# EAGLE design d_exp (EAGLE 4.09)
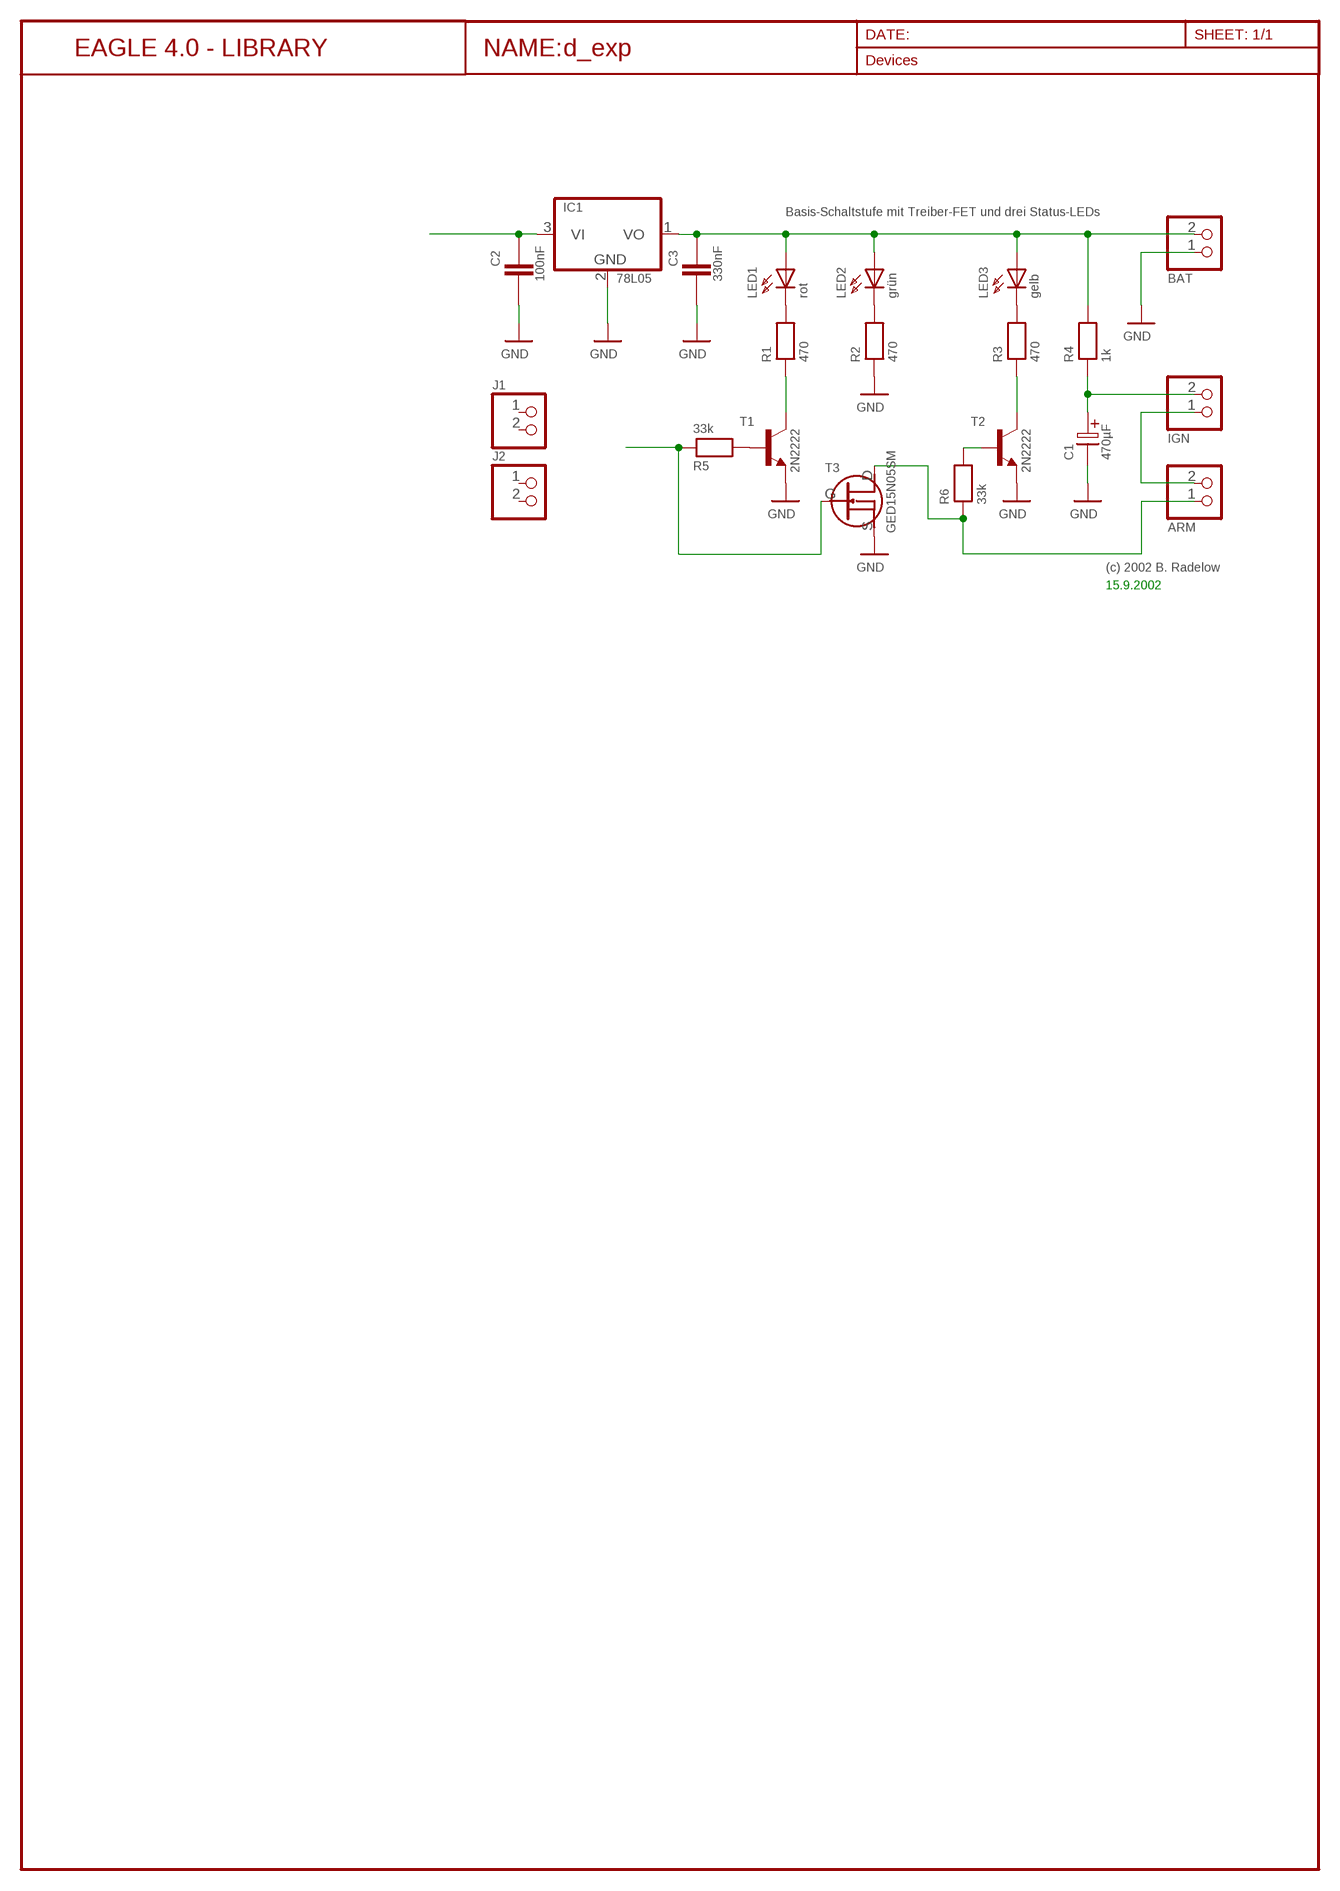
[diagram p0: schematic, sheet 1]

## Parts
ARM  PFOSTEN_1X2  [1X02]
BAT  PFOSTEN_1X2  [1X02]
C1  470µF  EC_470U  [E5-10,5]
C2  100nF  MKS2_10N-150N  [C5B2.5]
C3  330nF  MKS2_330N  [C5B3.5]
IC1  78L05  [TO92]
IGN  PFOSTEN_1X2  [1X02]
J1  PFOSTEN_1X2  [1X02]
J2  PFOSTEN_1X2  [1X02]
LED1  rot  LED_3MM  [LED3MM]
LED2  grün  LED_3MM  [LED3MM]
LED3  gelb  LED_3MM  [LED3MM]
R1  470  R7,5  [0207/7]
R2  470  R7,5  [0207/7]
R3  470  R7,5  [0207/7]
R4  1k  R7,5  [0207/7]
R5  33k  R7,5  [0207/7]
R6  33k  R7,5  [0207/7]
T1  2N2222  [TO18]
T2  2N2222  [TO18]
T3  GED15N05SM  [TO252]

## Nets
5VOLT: C2.1 IC1.3(VI)
GND: BAT.1 C1.- C2.2 C3.2 IC1.2(GND) R2.1 T1.1(E) T2.1(E) T3.S
N$1: ARM.2 IGN.1
N$2: LED2.K(C) R2.2
N$3: LED1.K(C) R1.2
N$4: LED3.K(C) R3.2
N$6: R5.1 T3.G
N$8: ARM.1 R6.1 T3.D
N$11: C1.+ IGN.2 R4.1
N$17: R1.1 T1.3(C)
N$25: R3.1 T2.3(C)
N$27: R6.2 T2.2(B)
N$29: R5.2 T1.2(B)
V+: BAT.2 C3.1 IC1.1(VO) LED1.A LED2.A LED3.A R4.2
Unconnected: J1.1 J1.2 J2.1 J2.2

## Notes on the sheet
- Basis-Schaltstufe mit Treiber-FET und drei Status-LEDs
- (c) 2002 B. Radelow
- 15.9.2002

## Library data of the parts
ARM BAT IGN J1 J2 = _d_serie:PFOSTEN_1X2: Pfosten 2x1
C1 = _d_serie:EC_470U: 470µF 16V, Höhe 17mm
C2 = _d_serie:MKS2_10N-150N: WIMA MKS2 Folienkondensator
C3 = _d_serie:MKS2_330N: WIMA MKS2 Folienkondensator 330nF
IC1 = _d_serie:78L05: Voltage Regulator 5V
LED1-LED3 = _d_serie:LED_3MM
R1-R6 = _d_serie:R7,5: Widerstand 0,3 Watt liegend
T1 T2 = _d_serie:2N2222
T3 = _d_serie:GED15N05SM: N-Channel Power-FET

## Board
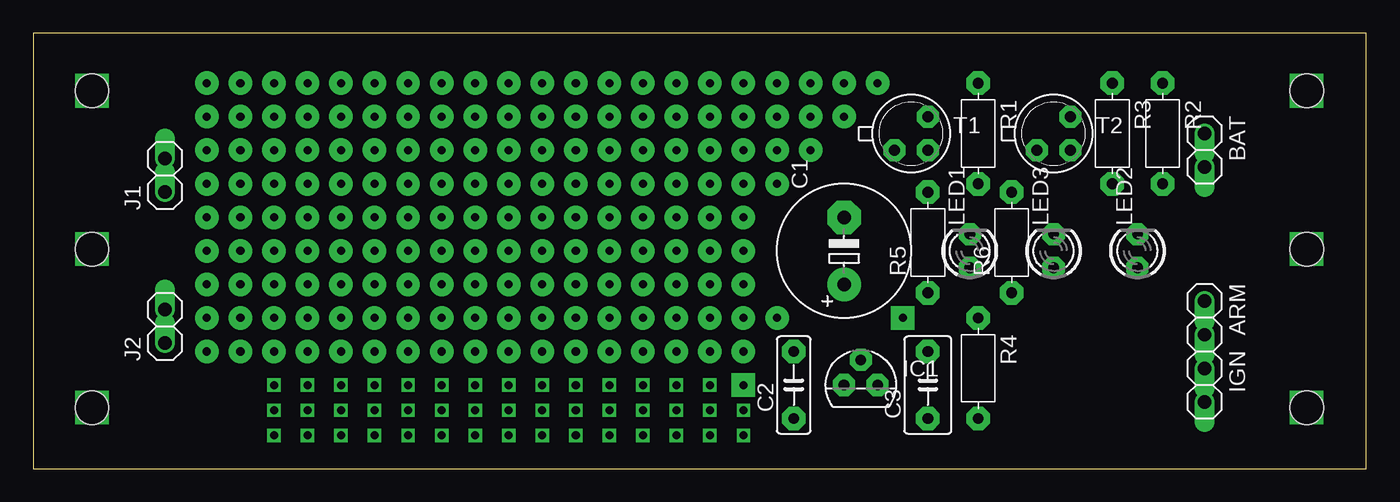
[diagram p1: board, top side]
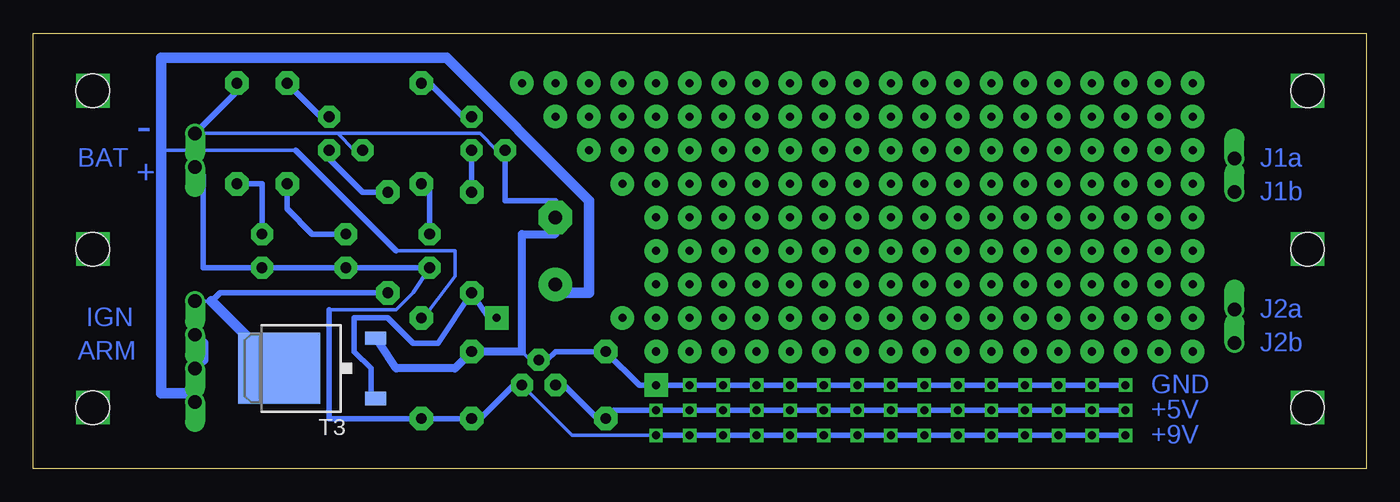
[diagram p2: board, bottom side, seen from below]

Size 101 x 33 mm. Coordinates in mm from the lower left corner, seen from the top.
Outline: 0,0 101,0 101,33 0,33 0,0
Copper layers used: Bottom
Holes 2.54 mm at 96.47,16.63 96.47,28.63 96.47,4.63 4.47,4.63 4.47,16.63 4.47,28.63
tRestrict: area -0.8,-0.6 to 100.8,33.7

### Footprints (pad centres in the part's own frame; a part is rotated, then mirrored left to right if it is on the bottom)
1X02 = drill 1.016 offset: 1 -1.27,0; 2 1.27,0
E5-10,5 = drill 1.016 pad 2.54 round: + -2.54,0 | drill 1.016 pad 2.54 octagon: - 2.54,0
C5B2.5 = drill 0.813 pad 1.778 octagon: 1 -2.54,0; 2 2.54,0
C5B3.5 = drill 0.813 pad 1.778 octagon: 1 -2.54,0; 2 2.54,0
TO92 = drill 0.813 pad 1.676 octagon: 1 1.27,0; 2 0,1.905; 3 -1.27,0
LED3MM = drill 0.813 pad 1.676 octagon: A -1.27,0; K 1.27,0
0207/7 = drill 0.813 pad 1.778 octagon: 1 -3.81,0; 2 3.81,0
TO18 = drill 0.813 pad 1.676 octagon: 1 -1.27,-1.27; 2 1.27,-1.27; 3 1.27,1.27
TO252 = smd 5.4 x 6.2: D 0,1.23 | smd 1 x 1.6: G -2.28,-6.07; S 2.28,-6.07

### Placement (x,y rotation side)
ARM  88.73,11.43 270 top
BAT  88.73,24.12 270 top
C1  61.43,16.5 90 top
C2  57.62,6.34 90 top
C3  67.78,6.34 90 top
IC1  62.7,6.34 0 top
IGN  88.73,6.34 270 top
J1  10,22.22 90 top
J2  10,10.79 90 top
LED1  70.95,16.5 90 top
LED2  83.66,16.5 90 top
LED3  77.3,16.5 90 top
R1  71.59,25.39 270 top
R2  85.56,25.39 270 top
R3  81.75,25.39 270 top
R4  71.59,7.62 270 top
R5  67.78,17.14 90 top
R6  74.13,17.14 90 top
T1  66.51,25.39 0 top
T2  77.3,25.39 0 top
T3  81.11,7.62 90 bottom

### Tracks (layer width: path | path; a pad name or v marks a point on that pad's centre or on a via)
5VOLT  (via drill 0.61 pad 1.02)
  Bottom 0.254: 60.8,6.34 IC1.3 | 58.25,3.8 C2.1 56.98,4.44
  Bottom 0.406: 58.25,3.8 60.8,6.34 | v18.25,4.44 v53.81,4.44 56.98,4.44
GND  (via drill 0.61 pad 1.02, 0.61 pad 1.78)
  Bottom 0.254: 62.06,8.25 IC1.2 63.34,8.25 63.97,8.89 | 74.77,9.52 T3.S | 61.43,20.31 C1.- 61.43,17.77 | 85.56,28.57 R2.1 | 77.94,25.39 76.67,24.12 T2.1 | 77.94,25.39 BAT.1 | 77.94,25.39 67.14,25.39 65.88,24.12 T1.1
  Bottom 0.406: 62.06,8.25 61.43,8.89 C2.2 55.08,6.34 v53.81,6.34 v18.25,6.34 | 61.43,20.31 65.24,20.31 T1.1 | BAT.1 85.56,28.57
  Bottom 0.61: 74.77,9.52 73.5,7.62 69.05,7.62 C3.2 63.97,8.89 63.97,17.77 61.43,17.77
N$1
  Bottom 0.254: IGN.1 88.1,8.25 | 88.1,9.52 ARM.2
  Bottom 0.813: 88.1,8.25 88.1,9.52
N$2
  Bottom 0.406: LED2.K 83.66,21.58 R2.2
N$3
  Bottom 0.254: 70.95,21.58 R1.2
  Bottom 0.406: LED1.K 70.95,21.58
N$4
  Bottom 0.406: LED3.K 79.84,17.77 81.75,19.68 R3.2
N$5  (via drill 0.61 pad 2.54)
  other vias: 96.47,28.63
N$6  (via drill 0.61 pad 1.78)
  Bottom 0.254: T3.G 75.4,5.71 | 66.51,11.43 v65.88,11.43
  Bottom 0.406: 75.4,5.71 75.4,7.62 76.67,8.89 76.67,11.43 74.13,11.43 72.22,9.52 70.32,9.52 R5.1 66.51,11.43
N$7  (via drill 0.61 pad 2.54)
  other vias: 96.47,16.63
N$8
  Bottom 0.254: 87.47,12.7 ARM.1 | 84.92,10.16 T3.D
  Bottom 0.406: R6.1 86.83,13.33 87.47,12.7
  Bottom 0.813: 87.47,12.7 84.92,10.16
N$9  (via drill 0.61 pad 2.54)
  other vias: 96.47,4.63
N$10  (via drill 0.61 pad 2.54)
  other vias: 4.47,4.63
N$11
  Bottom 0.254: 60.8,13.33 C1.+ | 73.5,16.5 69.05,16.5 69.05,14.6 70.95,12.06 R4.1 | 91.28,24.12 81.11,24.12 | 89.37,5.71 IGN.2
  Bottom 0.406: 81.11,24.12 73.5,16.5
  Bottom 0.813: 89.37,5.71 91.28,5.71 91.28,24.12 91.28,31.11 69.69,31.11 58.89,20.31 58.89,13.33 60.8,13.33
N$13  (via drill 0.61 pad 2.54)
  other vias: 4.47,16.63
N$14  (via drill 0.61 pad 2.54)
  other vias: 4.47,28.63
N$16  (via drill 0.61 pad 1.78)
  other vias: 13.17,29.2
N$17
  Bottom 0.254: T1.3 68.41,26.66 | 70.95,29.2 R1.1
  Bottom 0.406: 68.41,26.66 70.95,29.2
N$18  (via drill 0.61 pad 1.78)
  other vias: 13.17,26.66
N$19  (via drill 0.61 pad 1.78)
  other vias: 13.17,24.12
N$20  (via drill 0.61 pad 1.78)
  other vias: 13.17,21.58
N$21  (via drill 0.61 pad 1.78)
  other vias: 13.17,19.04
N$22  (via drill 0.61 pad 1.78)
  other vias: 13.17,16.5
N$23  (via drill 0.61 pad 1.78)
  other vias: 13.17,13.97
N$24  (via drill 0.61 pad 1.78)
  other vias: 13.17,11.43
N$25
  Bottom 0.254: 81.11,28.57 81.75,28.57 R3.1 | T2.3 79.21,26.66
  Bottom 0.406: 79.21,26.66 81.11,28.57
N$26  (via drill 0.61 pad 1.78)
  other vias: 13.17,8.89
N$27
  Bottom 0.254: 78.58,23.49 T2.2
  Bottom 0.406: 78.58,23.49 76.03,20.95 R6.2
N$29
  Bottom 0.406: R5.2 T1.2
N$30  (via drill 0.61 pad 1.78)
  other vias: 15.71,8.89
N$31  (via drill 0.61 pad 1.78)
  other vias: 15.71,11.43
N$32  (via drill 0.61 pad 1.78)
  other vias: 15.71,13.97
N$33  (via drill 0.61 pad 1.78)
  other vias: 15.71,16.5
N$34  (via drill 0.61 pad 1.78)
  other vias: 15.71,19.04
N$35  (via drill 0.61 pad 1.78)
  other vias: 15.71,21.58
N$36  (via drill 0.61 pad 1.78)
  other vias: 15.71,24.12
N$37  (via drill 0.61 pad 1.78)
  other vias: 15.71,26.66
N$38  (via drill 0.61 pad 1.78)
  other vias: 15.71,29.2
N$41  (via drill 0.61 pad 1.78)
  other vias: 18.25,29.2
N$42  (via drill 0.61 pad 1.78)
  other vias: 18.25,26.66
N$43  (via drill 0.61 pad 1.78)
  other vias: 18.25,24.12
N$44  (via drill 0.61 pad 1.78)
  other vias: 18.25,21.58
N$45  (via drill 0.61 pad 1.78)
  other vias: 18.25,19.04
N$46  (via drill 0.61 pad 1.78)
  other vias: 18.25,16.5
N$47  (via drill 0.61 pad 1.78)
  other vias: 18.25,13.97
N$48  (via drill 0.61 pad 1.78)
  other vias: 18.25,11.43
N$49  (via drill 0.61 pad 1.78)
  other vias: 18.25,8.89
N$51  (via drill 0.61 pad 1.02)
  other vias: 20.79,6.34
N$52  (via drill 0.61 pad 1.78)
  other vias: 20.79,8.89
N$53  (via drill 0.61 pad 1.78)
  other vias: 20.79,11.43
N$54  (via drill 0.61 pad 1.78)
  other vias: 20.79,13.97
N$55  (via drill 0.61 pad 1.78)
  other vias: 20.79,16.5
N$56  (via drill 0.61 pad 1.78)
  other vias: 20.79,19.04
N$57  (via drill 0.61 pad 1.78)
  other vias: 20.79,21.58
N$58  (via drill 0.61 pad 1.78)
  other vias: 20.79,24.12
N$59  (via drill 0.61 pad 1.78)
  other vias: 20.79,26.66
N$60  (via drill 0.61 pad 1.78)
  other vias: 20.79,29.2
N$63  (via drill 0.61 pad 1.78)
  other vias: 23.33,29.2
N$64  (via drill 0.61 pad 1.78)
  other vias: 23.33,26.66
N$65  (via drill 0.61 pad 1.78)
  other vias: 23.33,24.12
N$66  (via drill 0.61 pad 1.78)
  other vias: 23.33,21.58
N$67  (via drill 0.61 pad 1.78)
  other vias: 23.33,19.04
N$68  (via drill 0.61 pad 1.78)
  other vias: 23.33,16.5
N$69  (via drill 0.61 pad 1.78)
  other vias: 23.33,13.97
N$70  (via drill 0.61 pad 1.78)
  other vias: 23.33,11.43
N$71  (via drill 0.61 pad 1.78)
  other vias: 23.33,8.89
N$72  (via drill 0.61 pad 1.02)
  other vias: 23.33,6.34
N$73  (via drill 0.61 pad 1.02)
  other vias: 25.87,6.34
N$74  (via drill 0.61 pad 1.78)
  other vias: 25.87,8.89
N$75  (via drill 0.61 pad 1.78)
  other vias: 25.87,11.43
N$76  (via drill 0.61 pad 1.78)
  other vias: 25.87,13.97
N$77  (via drill 0.61 pad 1.78)
  other vias: 25.87,16.5
N$78  (via drill 0.61 pad 1.78)
  other vias: 25.87,19.04
N$79  (via drill 0.61 pad 1.78)
  other vias: 25.87,21.58
N$80  (via drill 0.61 pad 1.78)
  other vias: 25.87,24.12
N$81  (via drill 0.61 pad 1.78)
  other vias: 25.87,26.66
N$82  (via drill 0.61 pad 1.78)
  other vias: 25.87,29.2
N$85  (via drill 0.61 pad 1.78)
  other vias: 28.41,29.2
N$86  (via drill 0.61 pad 1.78)
  other vias: 28.41,26.66
N$87  (via drill 0.61 pad 1.78)
  other vias: 28.41,24.12
N$88  (via drill 0.61 pad 1.78)
  other vias: 28.41,21.58
N$89  (via drill 0.61 pad 1.78)
  other vias: 28.41,19.04
N$90  (via drill 0.61 pad 1.78)
  other vias: 28.41,16.5
N$91  (via drill 0.61 pad 1.78)
  other vias: 28.41,13.97
N$92  (via drill 0.61 pad 1.78)
  other vias: 28.41,11.43
N$93  (via drill 0.61 pad 1.78)
  other vias: 28.41,8.89
N$94  (via drill 0.61 pad 1.02)
  other vias: 28.41,6.34
N$95  (via drill 0.61 pad 1.02)
  other vias: 30.95,6.34
N$96  (via drill 0.61 pad 1.78)
  other vias: 30.95,8.89
N$97  (via drill 0.61 pad 1.78)
  other vias: 30.95,11.43
N$98  (via drill 0.61 pad 1.78)
  other vias: 30.95,13.97
N$99  (via drill 0.61 pad 1.78)
  other vias: 30.95,16.5
N$100  (via drill 0.61 pad 1.78)
  other vias: 30.95,19.04
N$101  (via drill 0.61 pad 1.78)
  other vias: 30.95,21.58
N$102  (via drill 0.61 pad 1.78)
  other vias: 30.95,24.12
N$103  (via drill 0.61 pad 1.78)
  other vias: 30.95,26.66
N$104  (via drill 0.61 pad 1.78)
  other vias: 30.95,29.2
N$107  (via drill 0.61 pad 1.78)
  other vias: 33.49,29.2
N$108  (via drill 0.61 pad 1.78)
  other vias: 33.49,26.66
N$109  (via drill 0.61 pad 1.78)
  other vias: 33.49,24.12
N$110  (via drill 0.61 pad 1.78)
  other vias: 33.49,21.58
N$111  (via drill 0.61 pad 1.78)
  other vias: 33.49,19.04
N$112  (via drill 0.61 pad 1.78)
  other vias: 33.49,16.5
N$113  (via drill 0.61 pad 1.78)
  other vias: 33.49,13.97
N$114  (via drill 0.61 pad 1.78)
  other vias: 33.49,11.43
N$115  (via drill 0.61 pad 1.78)
  other vias: 33.49,8.89
N$116  (via drill 0.61 pad 1.02)
  other vias: 33.49,6.34
N$117  (via drill 0.61 pad 1.02)
  other vias: 36.03,6.34
N$118  (via drill 0.61 pad 1.78)
  other vias: 36.03,8.89
N$119  (via drill 0.61 pad 1.78)
  other vias: 36.03,11.43
N$120  (via drill 0.61 pad 1.78)
  other vias: 36.03,13.97
N$121  (via drill 0.61 pad 1.78)
  other vias: 36.03,16.5
N$122  (via drill 0.61 pad 1.78)
  other vias: 36.03,19.04
N$123  (via drill 0.61 pad 1.78)
  other vias: 36.03,21.58
N$124  (via drill 0.61 pad 1.78)
  other vias: 36.03,24.12
N$125  (via drill 0.61 pad 1.78)
  other vias: 36.03,26.66
N$126  (via drill 0.61 pad 1.78)
  other vias: 36.03,29.2
N$129  (via drill 0.61 pad 1.78)
  other vias: 38.57,29.2
N$130  (via drill 0.61 pad 1.78)
  other vias: 38.57,26.66
N$131  (via drill 0.61 pad 1.78)
  other vias: 38.57,24.12
N$132  (via drill 0.61 pad 1.78)
  other vias: 38.57,21.58
N$133  (via drill 0.61 pad 1.78)
  other vias: 38.57,19.04
N$134  (via drill 0.61 pad 1.78)
  other vias: 38.57,16.5
N$135  (via drill 0.61 pad 1.78)
  other vias: 38.57,13.97
N$136  (via drill 0.61 pad 1.78)
  other vias: 38.57,11.43
N$137  (via drill 0.61 pad 1.78)
  other vias: 38.57,8.89
N$138  (via drill 0.61 pad 1.02)
  other vias: 38.57,6.34
N$139  (via drill 0.61 pad 1.02)
  other vias: 41.11,6.34
N$140  (via drill 0.61 pad 1.78)
  other vias: 41.11,8.89
N$141  (via drill 0.61 pad 1.78)
  other vias: 41.11,11.43
N$142  (via drill 0.61 pad 1.78)
  other vias: 41.11,13.97
N$143  (via drill 0.61 pad 1.78)
  other vias: 41.11,16.5
N$144  (via drill 0.61 pad 1.78)
  other vias: 41.11,19.04
N$145  (via drill 0.61 pad 1.78)
  other vias: 41.11,21.58
N$146  (via drill 0.61 pad 1.78)
  other vias: 41.11,24.12
N$147  (via drill 0.61 pad 1.78)
  other vias: 41.11,26.66
N$148  (via drill 0.61 pad 1.78)
  other vias: 41.11,29.2
N$151  (via drill 0.61 pad 1.78)
  other vias: 43.65,29.2
N$152  (via drill 0.61 pad 1.78)
  other vias: 43.65,26.66
N$153  (via drill 0.61 pad 1.78)
  other vias: 43.65,24.12
N$154  (via drill 0.61 pad 1.78)
  other vias: 43.65,21.58
N$155  (via drill 0.61 pad 1.78)
  other vias: 43.65,19.04
N$156  (via drill 0.61 pad 1.78)
  other vias: 43.65,16.5
N$157  (via drill 0.61 pad 1.78)
  other vias: 43.65,13.97
N$158  (via drill 0.61 pad 1.78)
  other vias: 43.65,11.43
N$159  (via drill 0.61 pad 1.78)
  other vias: 43.65,8.89
N$160  (via drill 0.61 pad 1.02)
  other vias: 43.65,6.34
N$161  (via drill 0.61 pad 1.02)
  other vias: 46.19,6.34
N$162  (via drill 0.61 pad 1.78)
  other vias: 46.19,8.89
N$163  (via drill 0.61 pad 1.78)
  other vias: 46.19,11.43
N$164  (via drill 0.61 pad 1.78)
  other vias: 46.19,13.97
N$165  (via drill 0.61 pad 1.78)
  other vias: 46.19,16.5
N$166  (via drill 0.61 pad 1.78)
  other vias: 46.19,19.04
N$167  (via drill 0.61 pad 1.78)
  other vias: 46.19,21.58
N$168  (via drill 0.61 pad 1.78)
  other vias: 46.19,24.12
N$169  (via drill 0.61 pad 1.78)
  other vias: 46.19,26.66
N$170  (via drill 0.61 pad 1.78)
  other vias: 46.19,29.2
N$173  (via drill 0.61 pad 1.78)
  other vias: 48.73,29.2
N$174  (via drill 0.61 pad 1.78)
  other vias: 48.73,26.66
N$175  (via drill 0.61 pad 1.78)
  other vias: 48.73,24.12
N$176  (via drill 0.61 pad 1.78)
  other vias: 48.73,21.58
N$177  (via drill 0.61 pad 1.78)
  other vias: 48.73,19.04
N$178  (via drill 0.61 pad 1.78)
  other vias: 48.73,16.5
N$179  (via drill 0.61 pad 1.78)
  other vias: 48.73,13.97
N$180  (via drill 0.61 pad 1.78)
  other vias: 48.73,11.43
N$181  (via drill 0.61 pad 1.78)
  other vias: 48.73,8.89
N$182  (via drill 0.61 pad 1.02)
  other vias: 48.73,6.34
N$183  (via drill 0.61 pad 1.02)
  other vias: 51.27,6.34
N$184  (via drill 0.61 pad 1.78)
  other vias: 51.27,8.89
N$185  (via drill 0.61 pad 1.78)
  other vias: 51.27,11.43
N$186  (via drill 0.61 pad 1.78)
  other vias: 51.27,13.97
N$187  (via drill 0.61 pad 1.78)
  other vias: 51.27,16.5
N$188  (via drill 0.61 pad 1.78)
  other vias: 51.27,19.04
N$189  (via drill 0.61 pad 1.78)
  other vias: 51.27,21.58
N$190  (via drill 0.61 pad 1.78)
  other vias: 51.27,24.12
N$191  (via drill 0.61 pad 1.78)
  other vias: 51.27,26.66
N$192  (via drill 0.61 pad 1.78)
  other vias: 51.27,29.2
N$195  (via drill 0.61 pad 1.78)
  other vias: 53.81,8.89
N$196  (via drill 0.61 pad 1.78)
  other vias: 53.81,11.43
N$197  (via drill 0.61 pad 1.78)
  other vias: 53.81,13.97
N$198  (via drill 0.61 pad 1.78)
  other vias: 53.81,16.5
N$199  (via drill 0.61 pad 1.78)
  other vias: 53.81,19.04
N$200  (via drill 0.61 pad 1.78)
  other vias: 53.81,21.58
N$201  (via drill 0.61 pad 1.78)
  other vias: 53.81,24.12
N$202  (via drill 0.61 pad 1.78)
  other vias: 53.81,26.66
N$203  (via drill 0.61 pad 1.78)
  other vias: 53.81,29.2
N$209  (via drill 0.61 pad 1.78)
  other vias: 56.35,29.2
N$210  (via drill 0.61 pad 1.78)
  other vias: 58.89,29.2
N$211  (via drill 0.61 pad 1.78)
  other vias: 61.43,29.2
N$212  (via drill 0.61 pad 1.78)
  other vias: 63.97,29.2
N$213  (via drill 0.61 pad 1.78)
  other vias: 56.35,26.66
N$214  (via drill 0.61 pad 1.78)
  other vias: 58.89,26.66
N$215  (via drill 0.61 pad 1.78)
  other vias: 61.43,26.66
N$216  (via drill 0.61 pad 1.78)
  other vias: 56.35,24.12
N$217  (via drill 0.61 pad 1.78)
  other vias: 58.89,24.12
N$218  (via drill 0.61 pad 1.78)
  other vias: 56.35,21.58
N$222  (via drill 0.61 pad 1.78)
  other vias: 56.35,11.43
N$224  (via drill 0.61 pad 1.02)
  other vias: 51.27,4.44
N$225  (via drill 0.61 pad 1.02)
  other vias: 48.73,4.44
N$229  (via drill 0.61 pad 1.02)
  other vias: 46.19,4.44
N$230  (via drill 0.61 pad 1.02)
  other vias: 43.65,4.44
N$231  (via drill 0.61 pad 1.02)
  other vias: 41.11,4.44
N$232  (via drill 0.61 pad 1.02)
  other vias: 46.19,2.54
N$233  (via drill 0.61 pad 1.02)
  other vias: 43.65,2.54
N$234  (via drill 0.61 pad 1.02)
  other vias: 41.11,2.54
N$235  (via drill 0.61 pad 1.02)
  other vias: 38.57,4.44
N$236  (via drill 0.61 pad 1.02)
  other vias: 36.03,4.44
N$237  (via drill 0.61 pad 1.02)
  other vias: 33.49,4.44
N$238  (via drill 0.61 pad 1.02)
  other vias: 38.57,2.54
N$239  (via drill 0.61 pad 1.02)
  other vias: 36.03,2.54
N$240  (via drill 0.61 pad 1.02)
  other vias: 33.49,2.54
N$241  (via drill 0.61 pad 1.02)
  other vias: 30.95,4.44
N$242  (via drill 0.61 pad 1.02)
  other vias: 28.41,4.44
N$243  (via drill 0.61 pad 1.02)
  other vias: 25.87,4.44
N$244  (via drill 0.61 pad 1.02)
  other vias: 30.95,2.54
N$245  (via drill 0.61 pad 1.02)
  other vias: 28.41,2.54
N$246  (via drill 0.61 pad 1.02)
  other vias: 25.87,2.54
N$247  (via drill 0.61 pad 1.02)
  other vias: 23.33,4.44
N$248  (via drill 0.61 pad 1.02)
  other vias: 20.79,4.44
N$250  (via drill 0.61 pad 1.02)
  other vias: 23.33,2.54
N$251  (via drill 0.61 pad 1.02)
  other vias: 20.79,2.54
V+  (via drill 0.61 pad 1.02)
  Bottom 0.254: 64.61,6.34 IC1.1 60.16,2.54 v53.81,2.54 | 67.14,3.8 C3.1 | 88.1,22.22 BAT.2 | 78.58,12.06 73.5,12.06 72.22,13.33 LED1.A
  Bottom 0.406: 64.61,6.34 67.14,3.8 | C3.1 R4.2 78.58,3.8 78.58,12.06 | LED1.A LED3.A LED2.A 88.1,15.24 88.1,22.22 | v53.81,2.54 v51.27,2.54 v48.73,2.54 v18.25,2.54

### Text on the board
Bottom: - | J1a | BAT | + | J1b | J2a | IGN | J2b | ARM | GND | +5V | +9V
